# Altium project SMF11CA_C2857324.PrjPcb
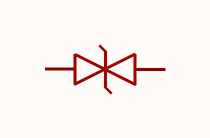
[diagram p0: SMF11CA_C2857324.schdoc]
1 sheet, 1 parts. Net scope: global (net labels, ports and power ports of the same name join across sheets).

## Sheet SMF11CA_C2857324.schdoc
size 127 x 101 mm

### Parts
D?  smf11ca_c2857324  [SOD-123FL_L2.8-W1.8-LS3.7-BI]  (value not drawn)

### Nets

Not connected (* = marked no-connect by the designer): D? 1 2

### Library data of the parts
D? = smf11ca_c2857324: 极性:双向;反向截止电压(Vrwm):11V;钳位电压:18.2V;峰值脉冲电流(Ipp):11A;峰值脉冲功率(Ppp):200W@10/1000us;击穿电压(VBR):12.2V;; Manufacturer: JSMSEMI(杰盛微); AddInBom: yes; ModelId: d105299b3871451c86f679efef28ff8f; ModelTransform: 145.669,70.866,0,0,0,0,0,0,0; Polarity: 双向; Reverse Stand-Off Voltage (Vrwm): 11V; Clamping Voltage: 18.2V; Peak Pulse Current (Ipp): 11A; Voltage - Breakdown: 12.2V; Reverse Leakage Current (Ir): 2.5uA; Number of Channels: 单路; Type: TVS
